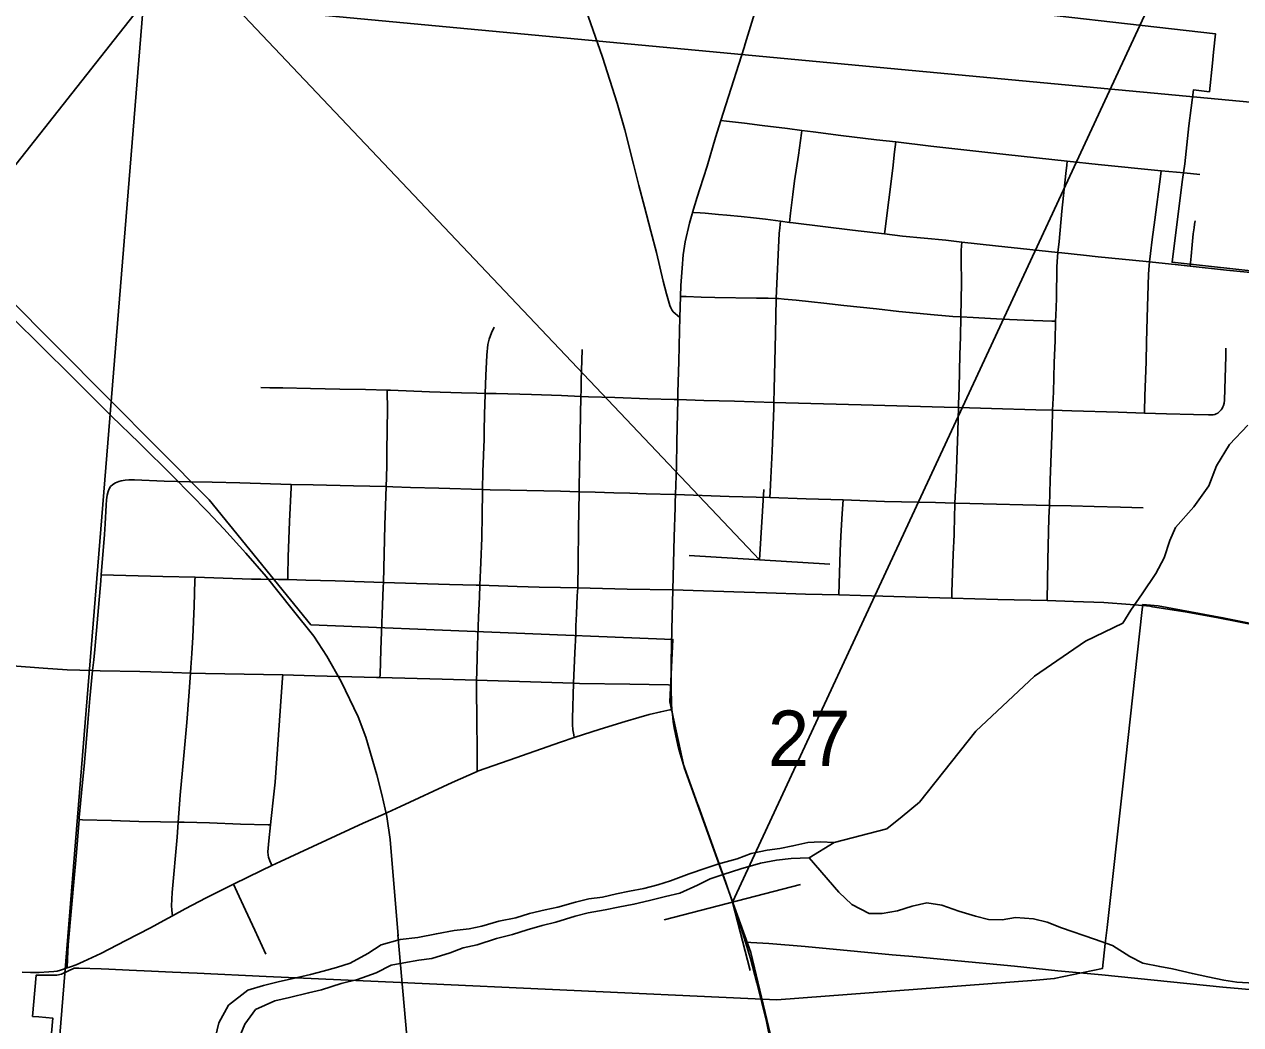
# Model space of a CAD drawing. Extents: x 0 to 1101, y 0 to 440.
# Drawn here: x 221.27 to 248.89, y 284.09 to 306.8 of the extents above; entities that cross this region are included whole.
import ezdxf

# ---------------------------------------------------------------- set-up
doc = ezdxf.new("R2010")
doc.units = 0
for name, color, linetype in [('GM_X_City_Street', 7, 'Continuous'), ('GM_X_Corporation', 7, 'Continuous'), ('GM_X_Major_River', 7, 'Continuous'), ('GM_X_Minor_River', 7, 'Continuous'), ('GM_X_Rail_Line', 7, 'Continuous'), ('GM_X_Section', 7, 'Continuous'), ('GM_X_Section_Text', 7, 'Continuous'), ('GM_X_State_Route', 7, 'Continuous'), ('GM_X_Township_Road', 7, 'Continuous'), ('GM_X_US_Route', 7, 'Continuous'), ('SH_Text', 7, 'Continuous'), ('SN_P_Signs', 7, 'Continuous')]:
    doc.layers.add(name, color=color, linetype=linetype)

msp = doc.modelspace()

# ---------------------------------------------------------------- linework, layer by layer
at = {"layer": 'GM_X_City_Street'}
for points in [[(237.085, 304.619), (237.213, 304.604), (237.624, 304.556), (238.02, 304.505), (238.602, 304.433), (238.923, 304.391), (239.179, 304.358), (239.807, 304.279), (240.622, 304.18), (241.057, 304.129), (241.854, 304.036), (243.554, 303.847), (244.951, 303.694), (245.653, 303.618), (247.089, 303.477), (247.61, 303.426)], [(238.642, 302.304), (238.667, 302.51), (238.718, 302.933), (238.761, 303.245), (238.846, 303.831), (238.914, 304.326), (238.923, 304.391)], [(240.804, 302.042), (240.811, 302.096), (240.9, 302.815), (240.99, 303.535), (241.031, 303.903), (241.057, 304.129)], [(244.495, 293.714), (244.512, 294.63), (244.536, 295.595), (244.546, 295.877), (244.567, 296.451), (244.609, 297.655), (244.619, 298.014), (244.62, 298.036), (244.637, 298.451), (244.655, 299.111), (244.678, 299.623), (244.689, 300.057), (244.693, 300.181), (244.705, 300.572), (244.719, 301.293), (244.728, 301.521), (244.738, 301.618), (244.765, 301.87), (244.83, 302.561), (244.921, 303.413), (244.941, 303.601), (244.951, 303.694)], [(246.703, 297.974), (246.704, 298.008), (246.717, 298.364), (246.746, 299.137), (246.752, 299.583), (246.768, 300.139), (246.801, 301.126), (246.813, 301.326), (246.822, 301.407), (246.841, 301.594), (246.882, 301.913), (246.942, 302.363), (247.071, 303.347), (247.089, 303.477)], [(236.441, 302.525), (236.615, 302.522), (236.732, 302.513), (237.028, 302.483), (237.219, 302.469), (237.545, 302.434), (237.824, 302.404), (238.099, 302.373), (238.442, 302.33), (238.642, 302.304), (238.729, 302.293), (240.077, 302.13), (240.804, 302.042), (241.213, 301.992), (242.194, 301.896), (242.555, 301.855), (243.322, 301.77), (244.1, 301.685), (244.738, 301.618), (244.828, 301.609), (245.319, 301.559), (245.656, 301.524), (246.744, 301.414), (246.822, 301.407)], [(238.196, 296.053), (238.204, 296.185), (238.217, 296.502), (238.25, 297.107), (238.266, 297.478), (238.285, 298.095), (238.287, 298.216), (238.293, 298.515), (238.323, 299.774), (238.34, 300.577), (238.357, 300.916), (238.393, 301.732), (238.413, 302.05), (238.426, 302.18), (238.442, 302.33)], [(242.328, 293.771), (242.333, 293.91), (242.361, 294.768), (242.382, 295.211), (242.391, 295.648), (242.399, 295.863), (242.402, 295.929), (242.429, 296.497), (242.465, 297.544), (242.473, 297.841), (242.483, 298.097), (242.486, 298.175), (242.494, 298.547), (242.516, 299.293), (242.525, 299.702), (242.534, 300.157), (242.548, 300.933), (242.543, 301.449), (242.543, 301.67), (242.555, 301.855)], [(236.168, 300.623), (236.301, 300.617), (236.636, 300.604), (236.949, 300.601), (237.897, 300.583), (238.156, 300.582), (238.34, 300.577), (238.392, 300.575), (238.52, 300.563), (238.796, 300.536), (239.145, 300.5), (239.424, 300.469), (239.882, 300.415), (240.617, 300.337), (241.131, 300.282), (241.931, 300.203), (242.184, 300.179), (242.357, 300.168), (242.534, 300.157), (242.818, 300.141), (243.475, 300.107), (243.985, 300.081), (244.603, 300.059), (244.689, 300.057)], [(231.554, 289.837), (231.547, 290.368), (231.542, 290.952), (231.536, 291.765), (231.539, 291.908), (231.543, 292.099), (231.554, 292.442), (231.56, 292.703), (231.578, 293.343), (231.602, 293.803), (231.614, 294.064), (231.634, 294.58), (231.653, 295.138), (231.661, 295.656), (231.672, 296.192), (231.673, 296.239), (231.679, 296.649), (231.694, 297), (231.702, 297.223), (231.707, 297.354), (231.707, 297.559), (231.718, 297.949), (231.734, 298.394), (231.735, 298.42), (231.75, 298.824), (231.774, 299.288), (231.796, 299.527), (231.825, 299.653), (231.879, 299.792), (231.937, 299.925)], [(233.754, 290.604), (233.744, 290.667), (233.725, 290.783), (233.717, 290.902), (233.717, 291.036), (233.742, 291.839), (233.768, 292.527), (233.788, 292.955), (233.795, 293.139), (233.805, 293.412), (233.823, 293.821), (233.834, 294.006), (233.846, 294.587), (233.855, 295.332), (233.868, 296.186), (233.869, 296.285), (233.878, 296.708), (233.882, 297.078), (233.891, 297.51), (233.907, 298.352), (233.909, 298.483), (233.916, 298.72), (233.927, 299.166), (233.933, 299.414)], [(248.396, 297.997), (248.415, 298.015), (248.446, 298.049), (248.468, 298.079), (248.486, 298.112), (248.499, 298.144), (248.514, 298.201), (248.524, 298.266), (248.553, 299.269), (248.557, 299.451)], [(226.641, 298.551), (226.841, 298.547), (227.14, 298.544), (227.766, 298.532), (228.433, 298.52), (229.018, 298.507), (229.509, 298.494), (229.584, 298.492), (230.47, 298.457), (231.197, 298.43), (231.54, 298.422), (231.735, 298.42), (231.986, 298.418), (232.784, 298.395), (233.467, 298.373), (233.907, 298.352), (234.081, 298.344), (234.68, 298.325), (235.429, 298.296), (236.025, 298.282), (236.105, 298.28)], [(229.422, 294.127), (229.456, 295.431), (229.486, 296.306), (229.49, 296.509), (229.498, 296.794), (229.502, 297.105), (229.513, 298.072), (229.509, 298.456), (229.509, 298.494)], [(236.105, 298.28), (236.699, 298.262), (237.392, 298.242), (238.287, 298.216), (238.562, 298.208), (240.272, 298.159), (242.155, 298.106), (242.483, 298.097), (243.23, 298.077), (244.236, 298.047), (244.62, 298.036), (245.057, 298.023), (246.108, 297.995), (246.703, 297.974), (247.208, 297.957), (247.823, 297.944), (248.157, 297.933), (248.198, 297.934), (248.24, 297.933), (248.268, 297.936), (248.303, 297.941), (248.335, 297.954), (248.37, 297.975), (248.396, 297.997)], [(223.013, 294.302), (223.088, 295.215), (223.105, 295.46), (223.127, 295.883), (223.134, 296.006), (223.151, 296.111), (223.169, 296.191), (223.195, 296.254), (223.226, 296.304), (223.273, 296.348), (223.336, 296.386), (223.409, 296.418)], [(223.409, 296.418), (223.467, 296.434), (223.558, 296.45), (223.642, 296.459), (223.771, 296.456), (224.445, 296.431), (225.024, 296.416), (225.531, 296.405), (226.161, 296.387), (227.329, 296.355), (227.823, 296.342), (228.742, 296.318), (229.486, 296.306), (229.637, 296.3), (230.039, 296.287), (230.68, 296.271), (231.673, 296.239), (231.843, 296.234), (232.299, 296.226), (233.441, 296.197), (233.868, 296.186), (234.234, 296.176), (234.658, 296.16), (235.019, 296.152), (235.389, 296.142), (236.033, 296.126), (236.055, 296.126)], [(227.248, 294.191), (227.249, 294.282), (227.257, 294.707), (227.289, 295.508), (227.326, 296.287), (227.329, 296.355)], [(236.055, 296.126), (237.274, 296.08), (238.196, 296.053), (239.025, 296.029), (239.861, 296.003), (240.802, 295.969), (241.963, 295.94), (242.402, 295.929), (242.742, 295.921), (244.546, 295.877), (245.041, 295.864), (245.56, 295.85), (246.162, 295.836), (246.679, 295.823)], [(239.763, 293.843), (239.797, 294.841), (239.811, 295.175), (239.842, 295.694), (239.861, 296.003)], [(224.631, 286.561), (224.625, 286.608), (224.614, 286.694), (224.611, 286.783), (224.626, 287.087), (224.736, 288.341), (224.763, 288.685), (224.809, 289.298), (224.86, 289.865), (224.955, 290.951), (225.003, 291.542), (225.041, 292.069), (225.051, 292.196), (225.069, 292.517), (225.091, 292.883), (225.126, 293.588), (225.142, 294.182), (225.143, 294.248)], [(229.342, 291.968), (229.345, 292.034), (229.366, 292.596), (229.418, 294.024), (229.422, 294.127)], [(216.294, 292.611), (216.437, 292.604), (216.731, 292.583), (217.12, 292.549), (218.053, 292.467), (219.02, 292.388), (220.056, 292.306), (220.999, 292.231), (221.694, 292.179), (222.238, 292.145), (222.813, 292.125)], [(222.242, 285.374), (222.247, 285.58), (222.264, 285.896), (222.403, 287.495), (222.425, 287.742), (222.448, 287.996), (222.509, 288.744), (222.513, 288.792), (222.579, 289.511), (222.623, 289.953), (222.661, 290.395), (222.715, 291.037), (222.756, 291.492), (222.813, 292.125)], [(222.813, 292.125), (222.992, 292.118), (223.891, 292.102), (224.641, 292.083), (225.041, 292.069), (225.378, 292.061), (226.699, 292.039), (227.137, 292.028), (227.864, 292.008), (229.267, 291.97), (229.342, 291.968), (230.758, 291.933), (231.539, 291.908), (233.742, 291.839), (233.873, 291.834), (235.019, 291.819), (235.897, 291.8), (235.954, 291.799)], [(226.889, 287.7), (226.871, 287.741), (226.841, 287.807), (226.814, 287.888), (226.802, 287.936), (226.796, 288.007), (226.816, 288.262), (226.857, 288.625), (226.873, 288.77), (226.928, 289.251), (226.965, 289.595), (227.019, 290.344), (227.087, 291.322), (227.132, 291.959), (227.137, 292.028)], [(221.215, 285.276), (221.403, 285.271), (221.602, 285.274), (221.821, 285.283), (221.937, 285.292), (222.01, 285.304), (222.09, 285.322), (222.202, 285.359), (222.242, 285.374), (222.314, 285.399), (222.443, 285.447), (222.612, 285.522), (223, 285.704), (223.569, 285.995), (224.133, 286.288), (224.434, 286.453), (224.631, 286.561), (224.916, 286.717), (225.397, 286.97), (226.017, 287.276), (226.651, 287.589), (226.889, 287.7), (227.085, 287.792), (227.505, 287.986), (228.963, 288.662), (229.414, 288.861), (229.809, 289.037), (230.984, 289.585), (231.554, 289.837), (231.562, 289.841), (232.281, 290.095), (233.444, 290.5), (233.754, 290.604), (234.345, 290.795), (234.915, 290.971), (235.224, 291.061), (235.455, 291.127), (235.719, 291.191), (235.929, 291.232), (235.973, 291.235)], [(222.509, 288.744), (222.59, 288.741), (223.248, 288.72), (223.87, 288.703), (224.361, 288.691), (224.763, 288.685), (224.899, 288.682), (225.474, 288.666), (226.173, 288.641), (226.804, 288.626), (226.857, 288.625)], [(226.754, 285.685), (226.503, 286.232), (226.29, 286.688), (226.102, 287.093), (226.017, 287.276)]]:
    msp.add_lwpolyline(points, dxfattribs=at)
at = {"layer": 'GM_X_Corporation'}
for points in [[(219.682, 301.859), (223.961, 307.274)], [(242.722, 307.224), (248.316, 306.586), (248.274, 306.17), (248.249, 305.921), (248.182, 305.268), (247.817, 305.31), (247.717, 304.499), (247.621, 303.631), (247.57, 303.281), (247.461, 302.435), (247.334, 301.397), (249.605, 301.147)], [(250.712, 292.874), (248.489, 293.326), (247.017, 293.596), (246.667, 293.626), (246.654, 293.517), (246.219, 289.568), (245.857, 286.29), (245.817, 285.933), (245.754, 285.362), (244.657, 285.134), (244.243, 285.098), (238.357, 284.651), (237.695, 284.682), (229.811, 285.041), (227.949, 285.126), (226.758, 285.181), (225.188, 285.252), (224.629, 285.278), (224.151, 285.299), (223.65, 285.323), (223.185, 285.343), (223.009, 285.352), (222.505, 285.366), (222.401, 285.367), (222.113, 285.23), (222.005, 285.214), (221.537, 285.212), (221.506, 284.866), (221.453, 284.273), (221.594, 284.261), (221.917, 284.232), (221.734, 282.187)]]:
    msp.add_lwpolyline(points, dxfattribs=at)
at = {"layer": 'GM_X_Major_River'}
for points in [[(249.05, 297.696), (248.634, 297.258), (248.343, 296.773), (248.166, 296.32), (247.83, 295.847), (247.414, 295.374), (247.284, 295.08), (247.154, 294.684), (246.967, 294.334), (246.653, 293.871), (246.398, 293.499), (246.212, 293.206), (245.366, 292.796)], [(241.596, 289.136), (242.877, 290.751), (244.21, 291.996), (245.366, 292.796)], [(239.655, 288.219), (240.855, 288.535), (241.203, 288.814), (241.596, 289.136)], [(239.655, 288.219), (239.348, 288.236), (239.063, 288.22), (238.721, 288.147), (238.424, 288.085), (238.138, 288.045), (237.773, 287.973), (237.452, 287.854), (237.04, 287.737), (236.742, 287.641), (236.364, 287.512), (235.94, 287.35), (235.654, 287.265), (235.334, 287.18), (235.014, 287.118), (234.717, 287.056), (234.397, 286.983), (234.089, 286.944), (233.781, 286.87), (233.38, 286.753), (233.094, 286.691), (232.74, 286.607), (232.431, 286.511), (232.043, 286.439), (231.654, 286.322), (231.368, 286.26), (231.026, 286.221), (230.627, 286.15), (230.204, 286.067), (229.805, 286.019), (229.37, 285.902), (229.07, 285.703), (228.668, 285.484), (228.359, 285.387), (228.05, 285.303), (227.764, 285.229), (227.467, 285.155), (227.033, 285.062), (226.701, 284.977), (226.346, 284.871), (225.907, 284.526), (225.682, 284.131), (225.607, 283.813)], [(226.105, 283.7), (226.273, 284.096), (226.519, 284.433), (226.955, 284.629), (227.286, 284.702), (227.721, 284.807), (228.018, 284.881), (228.464, 285.02), (228.83, 285.115), (229.254, 285.265), (229.599, 285.441), (229.885, 285.492), (230.227, 285.553), (230.524, 285.592), (230.936, 285.721), (231.234, 285.829), (231.554, 285.902), (231.989, 286.041), (232.355, 286.136), (232.687, 286.243), (233.03, 286.338), (233.339, 286.412), (233.774, 286.551), (234.071, 286.625), (234.459, 286.696), (234.756, 286.758), (235.11, 286.819), (235.464, 286.903), (235.83, 286.998), (236.15, 287.071), (236.552, 287.257), (236.84, 287.399), (237.137, 287.496), (237.538, 287.624), (237.984, 287.752), (238.35, 287.824), (238.68, 287.862), (239.09, 287.877), (239.655, 288.219)]]:
    msp.add_lwpolyline(points, dxfattribs=at)
at = {"layer": 'GM_X_Minor_River'}
for points in [[(239.09, 287.877), (239.767, 287.097), (240.057, 286.817), (240.45, 286.614), (240.746, 286.608), (241.1, 286.669), (241.432, 286.776), (241.763, 286.849), (242.103, 286.796), (242.487, 286.663), (242.871, 286.552), (243.165, 286.477), (243.472, 286.47), (243.78, 286.521), (244.189, 286.489), (244.494, 286.414), (244.821, 286.282), (245.572, 286.029)], [(245.572, 286.029), (245.98, 285.884), (246.375, 285.637), (246.669, 285.483), (247.055, 285.407), (247.34, 285.356), (247.794, 285.245), (248.146, 285.17), (248.51, 285.095), (248.806, 285.055), (249.194, 285.025)]]:
    msp.add_lwpolyline(points, dxfattribs=at)
at = {"layer": 'GM_X_Rail_Line'}
for points in [[(207.595, 347.721), (205.58, 337.301), (205.196, 335.14), (205.035, 333.563), (204.966, 332.345), (204.87, 330.138), (204.828, 328.104), (205.166, 325.582), (206.304, 320.469), (208.299, 315.584), (210.712, 311.388), (212.989, 308.669), (217.418, 304.098), (222.005, 299.489), (225.461, 296.005), (227.776, 293.168), (235.995, 292.835), (235.929, 291.413), (236.253, 289.925), (237.763, 285.722), (238.251, 283.697), (238.455, 282.445), (238.961, 279.059), (239.628, 275.669)], [(229.754, 286.107), (229.578, 288.291), (229.497, 288.816), (229.382, 289.31), (229.275, 289.759), (229.022, 290.617), (228.846, 291.077), (228.462, 291.878), (228.137, 292.456), (227.845, 292.905), (227.349, 293.524), (226.757, 294.261), (226.294, 294.794), (225.799, 295.342), (225.424, 295.74), (224.657, 296.522), (223.872, 297.296), (223.247, 297.902), (222.335, 298.81), (219.637, 301.477)], [(229.747, 286.123), (230.07, 282.543), (230.597, 276.505)]]:
    msp.add_lwpolyline(points, dxfattribs=at)
at = {"layer": 'GM_X_Section'}
for points in [[(257.267, 334.765), (254.28, 304.547), (223.979, 307.391), (226.76, 337.722)], [(254.28, 304.547), (251.23, 274.522), (221.544, 277.306), (223.979, 307.391)]]:
    msp.add_lwpolyline(points, close=True, dxfattribs=at)
at = {"layer": 'GM_X_State_Route'}
for points in [[(222.813, 292.125), (222.844, 292.372), (222.87, 292.602), (223.001, 294.161), (223.013, 294.302)], [(223.013, 294.302), (224.41, 294.262), (225.143, 294.248), (225.572, 294.233), (226.428, 294.205), (226.641, 294.202)], [(226.641, 294.202), (227.036, 294.196), (227.248, 294.191), (227.659, 294.181), (228.322, 294.161), (229.422, 294.127), (230.174, 294.104), (230.924, 294.08), (231.527, 294.065), (231.614, 294.064), (232.462, 294.034), (232.961, 294.023), (233.446, 294.011), (233.834, 294.006)], [(233.834, 294.006), (234.955, 293.977), (235.994, 293.958)], [(235.994, 293.958), (237.617, 293.907), (238.121, 293.892)], [(238.121, 293.892), (239.01, 293.864), (239.763, 293.843), (240.257, 293.829), (241.521, 293.793), (242.328, 293.771), (243.372, 293.742), (244.495, 293.714), (245.095, 293.695)], [(245.095, 293.695), (245.785, 293.673), (246.385, 293.63), (246.669, 293.604)], [(246.669, 293.604), (246.826, 293.587), (246.885, 293.577)], [(246.885, 293.577), (247.629, 293.457), (248.377, 293.326), (249.725, 293.063), (250.372, 292.934), (251.011, 292.807), (252.41, 292.536), (253.107, 292.415), (253.191, 292.403)], [(216.294, 292.611), (216.437, 292.604), (216.731, 292.583), (217.12, 292.549), (218.053, 292.467), (219.02, 292.388), (220.056, 292.306), (220.999, 292.231), (221.694, 292.179), (222.238, 292.145), (222.813, 292.125)]]:
    msp.add_lwpolyline(points, dxfattribs=at)
at = {"layer": 'GM_X_Township_Road'}
for p, q in [((247.61, 303.426), (247.966, 303.387)), ((246.822, 301.407), (247.318, 301.357))]:
    msp.add_line(p, q, dxfattribs=at)
for points in [[(236.151, 300.144), (236.048, 300.232), (236.005, 300.271), (235.972, 300.319), (235.949, 300.366), (235.929, 300.416), (235.848, 300.679), (235.778, 300.966), (235.625, 301.617), (235.493, 302.102), (235.352, 302.66), (235.222, 303.143), (235.1, 303.629), (234.904, 304.404), (234.732, 305.012), (234.4, 306.057), (234.229, 306.529), (234.077, 306.967), (233.888, 307.589), (233.703, 308.253), (233.469, 309.097), (232.909, 311.106), (232.555, 312.338)], [(247.745, 301.31), (247.769, 301.54), (247.789, 301.796), (247.811, 302.042), (247.831, 302.178), (247.844, 302.261), (247.856, 302.342)], [(247.318, 301.357), (247.405, 301.348), (247.745, 301.31), (248.57, 301.219), (249.431, 301.134), (249.582, 301.117)], [(237.643, 285.958), (237.768, 285.95), (238.172, 285.926), (238.998, 285.858), (240.188, 285.748), (240.975, 285.674), (241.442, 285.631), (242.309, 285.549), (243.753, 285.411)], [(243.753, 285.411), (244.741, 285.312), (245.738, 285.216)], [(245.738, 285.216), (248.485, 284.937), (249.781, 284.821), (250.694, 284.74), (251.35, 284.682), (251.412, 284.678)]]:
    msp.add_lwpolyline(points, dxfattribs=at)
at = {"layer": 'GM_X_US_Route'}
for p, q in [((236.146, 299.841), (236.151, 300.144)), ((238.017, 284.593), (238.003, 284.651))]:
    msp.add_line(p, q, dxfattribs=at)
for points in [[(237.612, 306.273), (237.639, 306.358), (237.822, 306.946), (238.007, 307.52)], [(236.151, 300.144), (236.168, 300.623), (236.179, 300.867), (236.203, 301.265), (236.227, 301.565), (236.276, 301.864), (236.372, 302.286), (236.434, 302.501), (236.441, 302.525), (236.547, 302.875), (236.611, 303.069), (236.776, 303.583), (236.963, 304.23), (237.085, 304.619), (237.195, 304.97), (237.612, 306.273)], [(236.044, 295.827), (236.048, 295.947), (236.055, 296.126), (236.081, 296.762), (236.086, 297.32), (236.105, 298.28), (236.108, 298.437), (236.134, 299.144), (236.146, 299.841)], [(235.994, 293.958), (236.023, 295.166), (236.044, 295.827)], [(236.555, 289.104), (236.232, 290.008), (236.147, 290.288), (236.108, 290.432), (236.059, 290.648), (236.025, 290.829), (236.003, 290.973), (235.985, 291.135), (235.973, 291.235), (235.966, 291.389), (235.954, 291.71), (235.954, 291.799), (235.954, 292.314), (235.969, 293.059), (235.994, 293.958)], [(238.003, 284.651), (237.902, 285.037), (237.756, 285.592), (237.643, 285.958), (237.5, 286.418), (237.197, 287.311), (236.575, 289.047), (236.555, 289.104)], [(239.635, 275.523), (239.268, 277.312), (239.075, 278.32), (238.892, 279.425), (238.614, 281.16), (238.461, 282.162), (238.22, 283.674), (238.122, 284.155), (238.017, 284.593)]]:
    msp.add_lwpolyline(points, dxfattribs=at)
at = {"layer": 'SH_Text'}
for p, q in [((237.963, 294.642), (220.208, 313.377)), ((247.337, 308.362), (237.349, 286.865))]:
    msp.add_line(p, q, dxfattribs=at)
at = {"layer": 'SN_P_Signs'}
for p, q in [((237.963, 294.642), (238.063, 296.239)), ((236.366, 294.742), (239.56, 294.542)), ((238.897, 287.266), (235.8, 286.463)), ((237.349, 286.865), (237.75, 285.316))]:
    msp.add_line(p, q, dxfattribs=at)

# ---------------------------------------------------------------- texts
at = {"layer": 'GM_X_Section_Text'}
msp.add_text('27', height=1.2557, rotation=0, dxfattribs=at).set_placement((238.156, 289.963))

doc.saveas('drawing.dxf')
